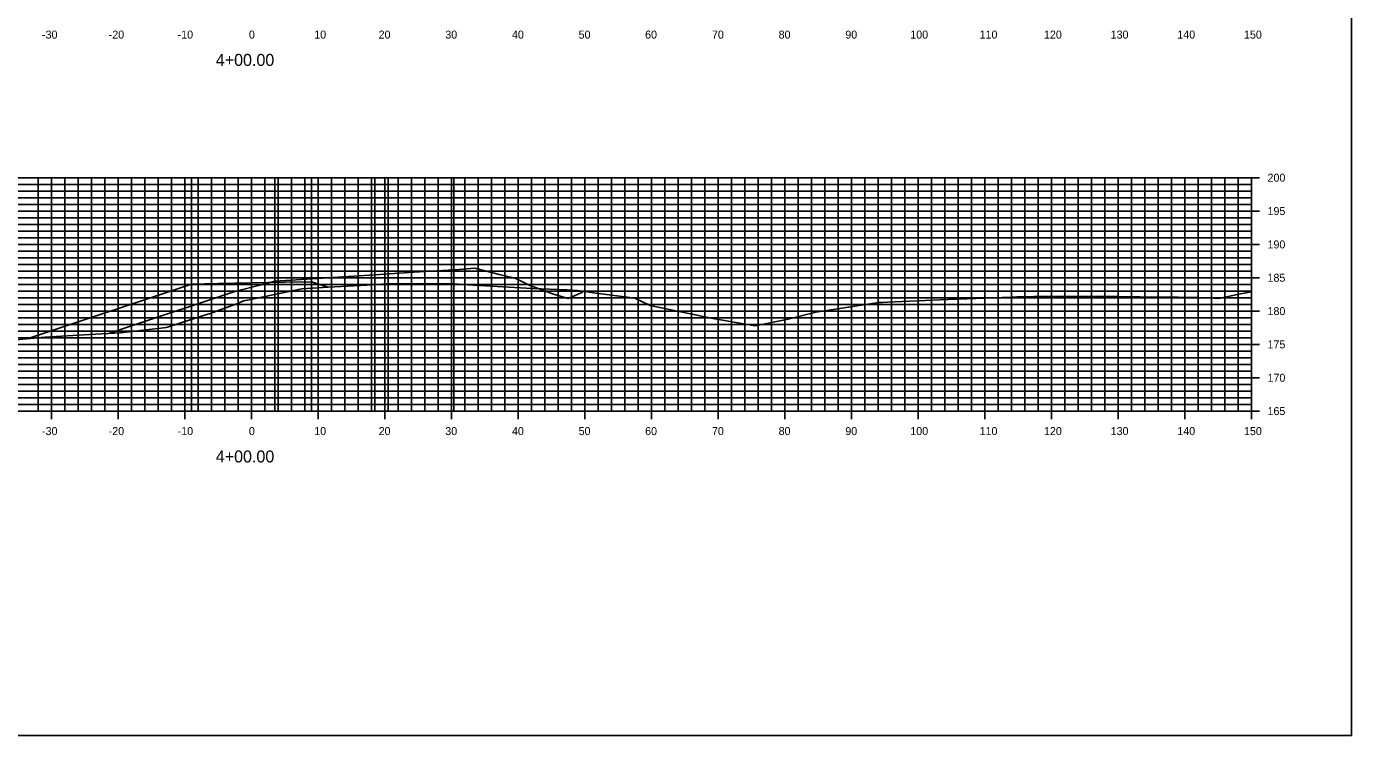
# Model space of a CAD drawing. Extents: x 1405440 to 1409538, y 1842123 to 1843178.
# Drawn here: x 1408848.9 to 1409047.6, y 1842723.5 to 1842829.8 of the extents above; entities that cross this region are included whole.
import ezdxf

# ---------------------------------------------------------------- set-up
doc = ezdxf.new("R2010")
doc.units = 0
for name, color, linetype in [('R_Axis Annot', 7, 'Continuous'), ('R_Exist Surface', 7, 'Continuous'), ('R_Grid_Minor', 7, 'Continuous'), ('R_Grid_Sta', 7, 'Continuous'), ('R_Grid_Tick', 7, 'Continuous'), ('R_Prop Surface', 7, 'Continuous'), ('Stage 3_Barrels_25 FT', 7, 'Continuous'), ('Stage 3_Construction', 7, 'Continuous'), ('Stage 3_Removal', 7, 'Continuous'), ('Stage 3_Stripe_4IN_White', 7, 'Continuous')]:
    doc.layers.add(name, color=color, linetype=linetype)

msp = doc.modelspace()

# ---------------------------------------------------------------- linework, layer by layer
for p, q in [((1408732.62, 1842807.12), (1409032.62, 1842807.12)), ((1408852.62, 1842772.12), (1408852.62, 1842807.12)), ((1408862.62, 1842772.12), (1408862.62, 1842807.12)), ((1408872.62, 1842772.12), (1408872.62, 1842807.12)), ((1408882.62, 1842772.12), (1408882.62, 1842807.12)), ((1408892.62, 1842772.12), (1408892.62, 1842807.12)), ((1408902.62, 1842772.12), (1408902.62, 1842807.12)), ((1408912.62, 1842772.12), (1408912.62, 1842807.12)), ((1408922.62, 1842772.12), (1408922.62, 1842807.12)), ((1408932.62, 1842772.12), (1408932.62, 1842807.12)), ((1408942.62, 1842772.12), (1408942.62, 1842807.12)), ((1408952.62, 1842772.12), (1408952.62, 1842807.12)), ((1408962.62, 1842772.12), (1408962.62, 1842807.12)), ((1408972.62, 1842772.12), (1408972.62, 1842807.12)), ((1408982.62, 1842772.12), (1408982.62, 1842807.12)), ((1408992.62, 1842772.12), (1408992.62, 1842807.12)), ((1409002.62, 1842772.12), (1409002.62, 1842807.12)), ((1409012.62, 1842772.12), (1409012.62, 1842807.12)), ((1409022.62, 1842772.12), (1409022.62, 1842807.12)), ((1409032.62, 1842772.12), (1409032.62, 1842807.12)), ((1409032.62, 1842772.12), (1409032.62, 1842807.12)), ((1408732.62, 1842802.12), (1409032.62, 1842802.12)), ((1408732.62, 1842797.12), (1409032.62, 1842797.12)), ((1408732.62, 1842792.12), (1409032.62, 1842792.12)), ((1408732.62, 1842787.12), (1409032.62, 1842787.12)), ((1408732.62, 1842782.12), (1409032.62, 1842782.12)), ((1408732.62, 1842777.12), (1409032.62, 1842777.12)), ((1408732.62, 1842772.12), (1409032.62, 1842772.12)), ((1408732.62, 1842772.12), (1409032.62, 1842772.12))]:
    msp.add_line(p, q)
msp.add_lwpolyline([(1408707.62, 1842723.47), (1409047.62, 1842723.47), (1409047.62, 1842943.47), (1408707.62, 1842943.47)], close=True)
at = {"layer": 'R_Exist Surface'}
msp.add_lwpolyline([(1408845.09, 1842782.62), (1408851.63, 1842783.23), (1408858.38, 1842783.61), (1408858.39, 1842783.61), (1408862.96, 1842783.86), (1408869.87, 1842784.68), (1408875.44, 1842786.44), (1408876.4, 1842786.77), (1408880.67, 1842788.33), (1408881.4, 1842788.64), (1408882, 1842788.75), (1408890.18, 1842790.47), (1408891.78, 1842790.55), (1408894.12, 1842790.7), (1408899.94, 1842791.01), (1408902.94, 1842791.2), (1408908.78, 1842791.21), (1408912.97, 1842791.19), (1408915.06, 1842791.05), (1408924.71, 1842790.51), (1408929.98, 1842790.29), (1408931.51, 1842790.22), (1408934.3, 1842789.83), (1408940.11, 1842789.05), (1408942.42, 1842787.97), (1408951.8, 1842786.02), (1408958.19, 1842784.91), (1408963.11, 1842785.89), (1408967.28, 1842786.97), (1408976.7, 1842788.41), (1408977.29, 1842788.43), (1408977.99, 1842788.44), (1408987.09, 1842788.85), (1408989.9, 1842788.97), (1408996.59, 1842789.23), (1408997.4, 1842789.27), (1409000.02, 1842789.29), (1409009.47, 1842789.35), (1409015.89, 1842789.27), (1409021.63, 1842789.19), (1409022.6, 1842789.17), (1409024.57, 1842789.17), (1409026.22, 1842789.11), (1409027.7, 1842789.03), (1409030.97, 1842789.69), (1409032.62, 1842789.99)], dxfattribs=at)
at = {"layer": 'R_Grid_Minor'}
for p, q in [((1408850.62, 1842772.12), (1408850.62, 1842807.12)), ((1408854.62, 1842772.12), (1408854.62, 1842807.12)), ((1408856.62, 1842772.12), (1408856.62, 1842807.12)), ((1408858.62, 1842772.12), (1408858.62, 1842807.12)), ((1408860.62, 1842772.12), (1408860.62, 1842807.12)), ((1408864.62, 1842772.12), (1408864.62, 1842807.12)), ((1408866.62, 1842772.12), (1408866.62, 1842807.12)), ((1408868.62, 1842772.12), (1408868.62, 1842807.12)), ((1408870.62, 1842772.12), (1408870.62, 1842807.12)), ((1408874.62, 1842772.12), (1408874.62, 1842807.12)), ((1408876.62, 1842772.12), (1408876.62, 1842807.12)), ((1408878.62, 1842772.12), (1408878.62, 1842807.12)), ((1408880.62, 1842772.12), (1408880.62, 1842807.12)), ((1408884.62, 1842772.12), (1408884.62, 1842807.12)), ((1408886.62, 1842772.12), (1408886.62, 1842807.12)), ((1408888.62, 1842772.12), (1408888.62, 1842807.12)), ((1408890.62, 1842772.12), (1408890.62, 1842807.12)), ((1408894.62, 1842772.12), (1408894.62, 1842807.12)), ((1408896.62, 1842772.12), (1408896.62, 1842807.12)), ((1408898.62, 1842772.12), (1408898.62, 1842807.12)), ((1408900.62, 1842772.12), (1408900.62, 1842807.12)), ((1408904.62, 1842772.12), (1408904.62, 1842807.12)), ((1408906.62, 1842772.12), (1408906.62, 1842807.12)), ((1408908.62, 1842772.12), (1408908.62, 1842807.12)), ((1408910.62, 1842772.12), (1408910.62, 1842807.12)), ((1408914.62, 1842772.12), (1408914.62, 1842807.12)), ((1408916.62, 1842772.12), (1408916.62, 1842807.12)), ((1408918.62, 1842772.12), (1408918.62, 1842807.12)), ((1408920.62, 1842772.12), (1408920.62, 1842807.12)), ((1408924.62, 1842772.12), (1408924.62, 1842807.12)), ((1408926.62, 1842772.12), (1408926.62, 1842807.12)), ((1408928.62, 1842772.12), (1408928.62, 1842807.12)), ((1408930.62, 1842772.12), (1408930.62, 1842807.12)), ((1408934.62, 1842772.12), (1408934.62, 1842807.12)), ((1408936.62, 1842772.12), (1408936.62, 1842807.12)), ((1408938.62, 1842772.12), (1408938.62, 1842807.12)), ((1408940.62, 1842772.12), (1408940.62, 1842807.12)), ((1408944.62, 1842772.12), (1408944.62, 1842807.12)), ((1408946.62, 1842772.12), (1408946.62, 1842807.12)), ((1408948.62, 1842772.12), (1408948.62, 1842807.12)), ((1408950.62, 1842772.12), (1408950.62, 1842807.12)), ((1408954.62, 1842772.12), (1408954.62, 1842807.12)), ((1408956.62, 1842772.12), (1408956.62, 1842807.12)), ((1408958.62, 1842772.12), (1408958.62, 1842807.12)), ((1408960.62, 1842772.12), (1408960.62, 1842807.12)), ((1408964.62, 1842772.12), (1408964.62, 1842807.12)), ((1408966.62, 1842772.12), (1408966.62, 1842807.12)), ((1408968.62, 1842772.12), (1408968.62, 1842807.12)), ((1408970.62, 1842772.12), (1408970.62, 1842807.12)), ((1408974.62, 1842772.12), (1408974.62, 1842807.12)), ((1408976.62, 1842772.12), (1408976.62, 1842807.12)), ((1408978.62, 1842772.12), (1408978.62, 1842807.12)), ((1408980.62, 1842772.12), (1408980.62, 1842807.12)), ((1408984.62, 1842772.12), (1408984.62, 1842807.12)), ((1408986.62, 1842772.12), (1408986.62, 1842807.12)), ((1408988.62, 1842772.12), (1408988.62, 1842807.12)), ((1408990.62, 1842772.12), (1408990.62, 1842807.12)), ((1408994.62, 1842772.12), (1408994.62, 1842807.12)), ((1408996.62, 1842772.12), (1408996.62, 1842807.12)), ((1408998.62, 1842772.12), (1408998.62, 1842807.12)), ((1409000.62, 1842772.12), (1409000.62, 1842807.12)), ((1409004.62, 1842772.12), (1409004.62, 1842807.12)), ((1409006.62, 1842772.12), (1409006.62, 1842807.12)), ((1409008.62, 1842772.12), (1409008.62, 1842807.12)), ((1409010.62, 1842772.12), (1409010.62, 1842807.12)), ((1409014.62, 1842772.12), (1409014.62, 1842807.12)), ((1409016.62, 1842772.12), (1409016.62, 1842807.12)), ((1409018.62, 1842772.12), (1409018.62, 1842807.12)), ((1409020.62, 1842772.12), (1409020.62, 1842807.12)), ((1409024.62, 1842772.12), (1409024.62, 1842807.12)), ((1409026.62, 1842772.12), (1409026.62, 1842807.12)), ((1409028.62, 1842772.12), (1409028.62, 1842807.12)), ((1409030.62, 1842772.12), (1409030.62, 1842807.12)), ((1408732.62, 1842806.12), (1409032.62, 1842806.12)), ((1408732.62, 1842805.12), (1409032.62, 1842805.12)), ((1408732.62, 1842804.12), (1409032.62, 1842804.12)), ((1408732.62, 1842803.12), (1409032.62, 1842803.12)), ((1408732.62, 1842801.12), (1409032.62, 1842801.12)), ((1408732.62, 1842800.12), (1409032.62, 1842800.12)), ((1408732.62, 1842799.12), (1409032.62, 1842799.12)), ((1408732.62, 1842798.12), (1409032.62, 1842798.12)), ((1408732.62, 1842796.12), (1409032.62, 1842796.12)), ((1408732.62, 1842795.12), (1409032.62, 1842795.12)), ((1408732.62, 1842794.12), (1409032.62, 1842794.12)), ((1408732.62, 1842793.12), (1409032.62, 1842793.12)), ((1408732.62, 1842791.12), (1409032.62, 1842791.12)), ((1408732.62, 1842790.12), (1409032.62, 1842790.12)), ((1408732.62, 1842789.12), (1409032.62, 1842789.12)), ((1408732.62, 1842788.12), (1409032.62, 1842788.12)), ((1408732.62, 1842786.12), (1409032.62, 1842786.12)), ((1408732.62, 1842785.12), (1409032.62, 1842785.12)), ((1408732.62, 1842784.12), (1409032.62, 1842784.12)), ((1408732.62, 1842783.12), (1409032.62, 1842783.12)), ((1408732.62, 1842781.12), (1409032.62, 1842781.12)), ((1408732.62, 1842780.12), (1409032.62, 1842780.12)), ((1408732.62, 1842779.12), (1409032.62, 1842779.12)), ((1408732.62, 1842778.12), (1409032.62, 1842778.12)), ((1408732.62, 1842776.12), (1409032.62, 1842776.12)), ((1408732.62, 1842775.12), (1409032.62, 1842775.12)), ((1408732.62, 1842774.12), (1409032.62, 1842774.12)), ((1408732.62, 1842773.12), (1409032.62, 1842773.12))]:
    msp.add_line(p, q, dxfattribs=at)
at = {"layer": 'R_Grid_Tick'}
for p, q in [((1409033.82, 1842807.12), (1409031.42, 1842807.12)), ((1409032.62, 1842806.12), (1409032.02, 1842806.12)), ((1409032.62, 1842805.12), (1409032.02, 1842805.12)), ((1409032.62, 1842804.12), (1409032.02, 1842804.12)), ((1409032.62, 1842803.12), (1409032.02, 1842803.12)), ((1409033.82, 1842802.12), (1409031.42, 1842802.12)), ((1409032.62, 1842801.12), (1409032.02, 1842801.12)), ((1409032.62, 1842800.12), (1409032.02, 1842800.12)), ((1409032.62, 1842799.12), (1409032.02, 1842799.12)), ((1409033.82, 1842797.12), (1409031.42, 1842797.12)), ((1409032.62, 1842798.12), (1409032.02, 1842798.12)), ((1409032.62, 1842796.12), (1409032.02, 1842796.12)), ((1409032.62, 1842795.12), (1409032.02, 1842795.12)), ((1409032.62, 1842794.12), (1409032.02, 1842794.12)), ((1409032.62, 1842793.12), (1409032.02, 1842793.12)), ((1409033.82, 1842792.12), (1409031.42, 1842792.12)), ((1409032.62, 1842791.12), (1409032.02, 1842791.12)), ((1409032.62, 1842790.12), (1409032.02, 1842790.12)), ((1409032.62, 1842789.12), (1409032.02, 1842789.12)), ((1409033.82, 1842787.12), (1409031.42, 1842787.12)), ((1409032.62, 1842788.12), (1409032.02, 1842788.12)), ((1409032.62, 1842786.12), (1409032.02, 1842786.12)), ((1409032.62, 1842785.12), (1409032.02, 1842785.12)), ((1409032.62, 1842784.12), (1409032.02, 1842784.12)), ((1409032.62, 1842783.12), (1409032.02, 1842783.12)), ((1409033.82, 1842782.12), (1409031.42, 1842782.12)), ((1409032.62, 1842781.12), (1409032.02, 1842781.12)), ((1409032.62, 1842780.12), (1409032.02, 1842780.12)), ((1409032.62, 1842779.12), (1409032.02, 1842779.12)), ((1409033.82, 1842777.12), (1409031.42, 1842777.12)), ((1409032.62, 1842778.12), (1409032.02, 1842778.12)), ((1409032.62, 1842776.12), (1409032.02, 1842776.12)), ((1409032.62, 1842775.12), (1409032.02, 1842775.12)), ((1408852.62, 1842770.92), (1408852.62, 1842773.32)), ((1408862.62, 1842770.92), (1408862.62, 1842773.32)), ((1408872.62, 1842770.92), (1408872.62, 1842773.32)), ((1408882.62, 1842770.92), (1408882.62, 1842773.32)), ((1408892.62, 1842770.92), (1408892.62, 1842773.32)), ((1408902.62, 1842770.92), (1408902.62, 1842773.32)), ((1408912.62, 1842770.92), (1408912.62, 1842773.32)), ((1408922.62, 1842770.92), (1408922.62, 1842773.32)), ((1408932.62, 1842770.92), (1408932.62, 1842773.32)), ((1408942.62, 1842770.92), (1408942.62, 1842773.32)), ((1408952.62, 1842770.92), (1408952.62, 1842773.32)), ((1408962.62, 1842770.92), (1408962.62, 1842773.32)), ((1408972.62, 1842770.92), (1408972.62, 1842773.32)), ((1408982.62, 1842770.92), (1408982.62, 1842773.32)), ((1408992.62, 1842770.92), (1408992.62, 1842773.32)), ((1409002.62, 1842770.92), (1409002.62, 1842773.32)), ((1409012.62, 1842770.92), (1409012.62, 1842773.32)), ((1409022.62, 1842770.92), (1409022.62, 1842773.32)), ((1409032.62, 1842774.12), (1409032.02, 1842774.12)), ((1409032.62, 1842773.12), (1409032.02, 1842773.12)), ((1409032.62, 1842770.92), (1409032.62, 1842773.32)), ((1408850.62, 1842772.12), (1408850.62, 1842772.72)), ((1408854.62, 1842772.12), (1408854.62, 1842772.72)), ((1408856.62, 1842772.12), (1408856.62, 1842772.72)), ((1408858.62, 1842772.12), (1408858.62, 1842772.72)), ((1408860.62, 1842772.12), (1408860.62, 1842772.72)), ((1408864.62, 1842772.12), (1408864.62, 1842772.72)), ((1408866.62, 1842772.12), (1408866.62, 1842772.72)), ((1408868.62, 1842772.12), (1408868.62, 1842772.72)), ((1408870.62, 1842772.12), (1408870.62, 1842772.72)), ((1408874.62, 1842772.12), (1408874.62, 1842772.72)), ((1408876.62, 1842772.12), (1408876.62, 1842772.72)), ((1408878.62, 1842772.12), (1408878.62, 1842772.72)), ((1408880.62, 1842772.12), (1408880.62, 1842772.72)), ((1408884.62, 1842772.12), (1408884.62, 1842772.72)), ((1408886.62, 1842772.12), (1408886.62, 1842772.72)), ((1408888.62, 1842772.12), (1408888.62, 1842772.72)), ((1408890.62, 1842772.12), (1408890.62, 1842772.72)), ((1408894.62, 1842772.12), (1408894.62, 1842772.72)), ((1408896.62, 1842772.12), (1408896.62, 1842772.72)), ((1408898.62, 1842772.12), (1408898.62, 1842772.72)), ((1408900.62, 1842772.12), (1408900.62, 1842772.72)), ((1408904.62, 1842772.12), (1408904.62, 1842772.72)), ((1408906.62, 1842772.12), (1408906.62, 1842772.72)), ((1408908.62, 1842772.12), (1408908.62, 1842772.72)), ((1408910.62, 1842772.12), (1408910.62, 1842772.72)), ((1408914.62, 1842772.12), (1408914.62, 1842772.72)), ((1408916.62, 1842772.12), (1408916.62, 1842772.72)), ((1408918.62, 1842772.12), (1408918.62, 1842772.72)), ((1408920.62, 1842772.12), (1408920.62, 1842772.72)), ((1408924.62, 1842772.12), (1408924.62, 1842772.72)), ((1408926.62, 1842772.12), (1408926.62, 1842772.72)), ((1408928.62, 1842772.12), (1408928.62, 1842772.72)), ((1408930.62, 1842772.12), (1408930.62, 1842772.72)), ((1408934.62, 1842772.12), (1408934.62, 1842772.72)), ((1408936.62, 1842772.12), (1408936.62, 1842772.72)), ((1408938.62, 1842772.12), (1408938.62, 1842772.72)), ((1408940.62, 1842772.12), (1408940.62, 1842772.72)), ((1408944.62, 1842772.12), (1408944.62, 1842772.72)), ((1408946.62, 1842772.12), (1408946.62, 1842772.72)), ((1408948.62, 1842772.12), (1408948.62, 1842772.72)), ((1408950.62, 1842772.12), (1408950.62, 1842772.72)), ((1408954.62, 1842772.12), (1408954.62, 1842772.72)), ((1408956.62, 1842772.12), (1408956.62, 1842772.72)), ((1408958.62, 1842772.12), (1408958.62, 1842772.72)), ((1408960.62, 1842772.12), (1408960.62, 1842772.72)), ((1408964.62, 1842772.12), (1408964.62, 1842772.72)), ((1408966.62, 1842772.12), (1408966.62, 1842772.72)), ((1408968.62, 1842772.12), (1408968.62, 1842772.72)), ((1408970.62, 1842772.12), (1408970.62, 1842772.72)), ((1408974.62, 1842772.12), (1408974.62, 1842772.72)), ((1408976.62, 1842772.12), (1408976.62, 1842772.72)), ((1408978.62, 1842772.12), (1408978.62, 1842772.72)), ((1408980.62, 1842772.12), (1408980.62, 1842772.72)), ((1408984.62, 1842772.12), (1408984.62, 1842772.72)), ((1408986.62, 1842772.12), (1408986.62, 1842772.72)), ((1408988.62, 1842772.12), (1408988.62, 1842772.72)), ((1408990.62, 1842772.12), (1408990.62, 1842772.72)), ((1408994.62, 1842772.12), (1408994.62, 1842772.72)), ((1408996.62, 1842772.12), (1408996.62, 1842772.72)), ((1408998.62, 1842772.12), (1408998.62, 1842772.72)), ((1409000.62, 1842772.12), (1409000.62, 1842772.72)), ((1409004.62, 1842772.12), (1409004.62, 1842772.72)), ((1409006.62, 1842772.12), (1409006.62, 1842772.72)), ((1409008.62, 1842772.12), (1409008.62, 1842772.72)), ((1409010.62, 1842772.12), (1409010.62, 1842772.72)), ((1409014.62, 1842772.12), (1409014.62, 1842772.72)), ((1409016.62, 1842772.12), (1409016.62, 1842772.72)), ((1409018.62, 1842772.12), (1409018.62, 1842772.72)), ((1409020.62, 1842772.12), (1409020.62, 1842772.72)), ((1409024.62, 1842772.12), (1409024.62, 1842772.72)), ((1409026.62, 1842772.12), (1409026.62, 1842772.72)), ((1409028.62, 1842772.12), (1409028.62, 1842772.72)), ((1409030.62, 1842772.12), (1409030.62, 1842772.72)), ((1409033.82, 1842772.12), (1409031.42, 1842772.12))]:
    msp.add_line(p, q, dxfattribs=at)
at = {"layer": 'R_Prop Surface'}
for points in [[(1408861.2, 1842783.77), (1408863.72, 1842784.61), (1408880.11, 1842790.08), (1408884.06, 1842791.07), (1408886.12, 1842791.59), (1408888.58, 1842791.75), (1408890.12, 1842791.85), (1408894.83, 1842792.15), (1408901.13, 1842792.56), (1408906.97, 1842792.94), (1408912.14, 1842793.28), (1408913.76, 1842793.38), (1408916.14, 1842793.54), (1408919.96, 1842792.58), (1408922.15, 1842792.04), (1408924.25, 1842790.99), (1408927.77, 1842789.72), (1408930.11, 1842789.01), (1408932.33, 1842789.98)], [(1408849.13, 1842783), (1408873.62, 1842791.16), (1408877.62, 1842791.24), (1408882.62, 1842791.34), (1408887.62, 1842791.44), (1408891.62, 1842791.52), (1408894.09, 1842790.7)]]:
    msp.add_lwpolyline(points, dxfattribs=at)
at = {"layer": 'Stage 3_Barrels_25 FT'}
msp.add_line((1408903.14, 1842772.12), (1408903.14, 1842807.12), dxfattribs=at)
at = {"layer": 'Stage 3_Construction'}
for p, q in [((1408886.13, 1842772.12), (1408886.13, 1842807.12)), ((1408901.14, 1842772.12), (1408901.14, 1842807.12))]:
    msp.add_line(p, q, dxfattribs=at)
at = {"layer": 'Stage 3_Removal'}
for p, q in [((1408873.62, 1842772.12), (1408873.62, 1842807.12)), ((1408891.62, 1842772.12), (1408891.62, 1842807.12))]:
    msp.add_line(p, q, dxfattribs=at)
at = {"layer": 'Stage 3_Stripe_4IN_White'}
msp.add_line((1408912.97, 1842772.12), (1408912.97, 1842807.12), dxfattribs=at)

# ---------------------------------------------------------------- texts
at = {"layer": 'R_Axis Annot'}
for s, p in [('-30', (1408851.2, 1842827.99)), ('-20', (1408861.2, 1842827.99)), ('-10', (1408871.54, 1842827.99)), ('0', (1408882.23, 1842827.99)), ('10', (1408892.03, 1842827.99)), ('20', (1408901.69, 1842827.99)), ('30', (1408911.69, 1842827.99)), ('40', (1408921.69, 1842827.99)), ('50', (1408931.69, 1842827.99)), ('60', (1408941.66, 1842827.99)), ('70', (1408951.69, 1842827.99)), ('80', (1408961.69, 1842827.99)), ('90', (1408971.69, 1842827.99)), ('100', (1408981.44, 1842827.99)), ('110', (1408991.83, 1842827.99)), ('120', (1409001.49, 1842827.99)), ('130', (1409011.49, 1842827.99)), ('140', (1409021.49, 1842827.99)), ('150', (1409031.49, 1842827.99)), ('200', (1409035.02, 1842806.52)), ('195', (1409035.02, 1842801.52)), ('190', (1409035.02, 1842796.52)), ('185', (1409035.02, 1842791.52)), ('180', (1409035.02, 1842786.52)), ('175', (1409035.02, 1842781.52)), ('170', (1409035.02, 1842776.52)), ('165', (1409035.02, 1842771.52)), ('-30', (1408851.2, 1842768.52)), ('-20', (1408861.2, 1842768.52)), ('-10', (1408871.54, 1842768.52)), ('0', (1408882.23, 1842768.52)), ('10', (1408892.03, 1842768.52)), ('20', (1408901.69, 1842768.52)), ('30', (1408911.69, 1842768.52)), ('40', (1408921.69, 1842768.52)), ('50', (1408931.69, 1842768.52)), ('60', (1408941.66, 1842768.52)), ('70', (1408951.69, 1842768.52)), ('80', (1408961.69, 1842768.52)), ('90', (1408971.69, 1842768.52)), ('100', (1408981.44, 1842768.52)), ('110', (1408991.83, 1842768.52)), ('120', (1409001.49, 1842768.52)), ('130', (1409011.49, 1842768.52)), ('140', (1409021.49, 1842768.52)), ('150', (1409031.49, 1842768.52))]:
    msp.add_text(s, height=1.2, dxfattribs=at).set_placement(p)
at = {"layer": 'R_Grid_Sta'}
for p in [(1408877.27, 1842823.89), (1408877.27, 1842764.42)]:
    msp.add_text('4+00.00', height=1.8, dxfattribs=at).set_placement(p)

doc.saveas('drawing.dxf')
